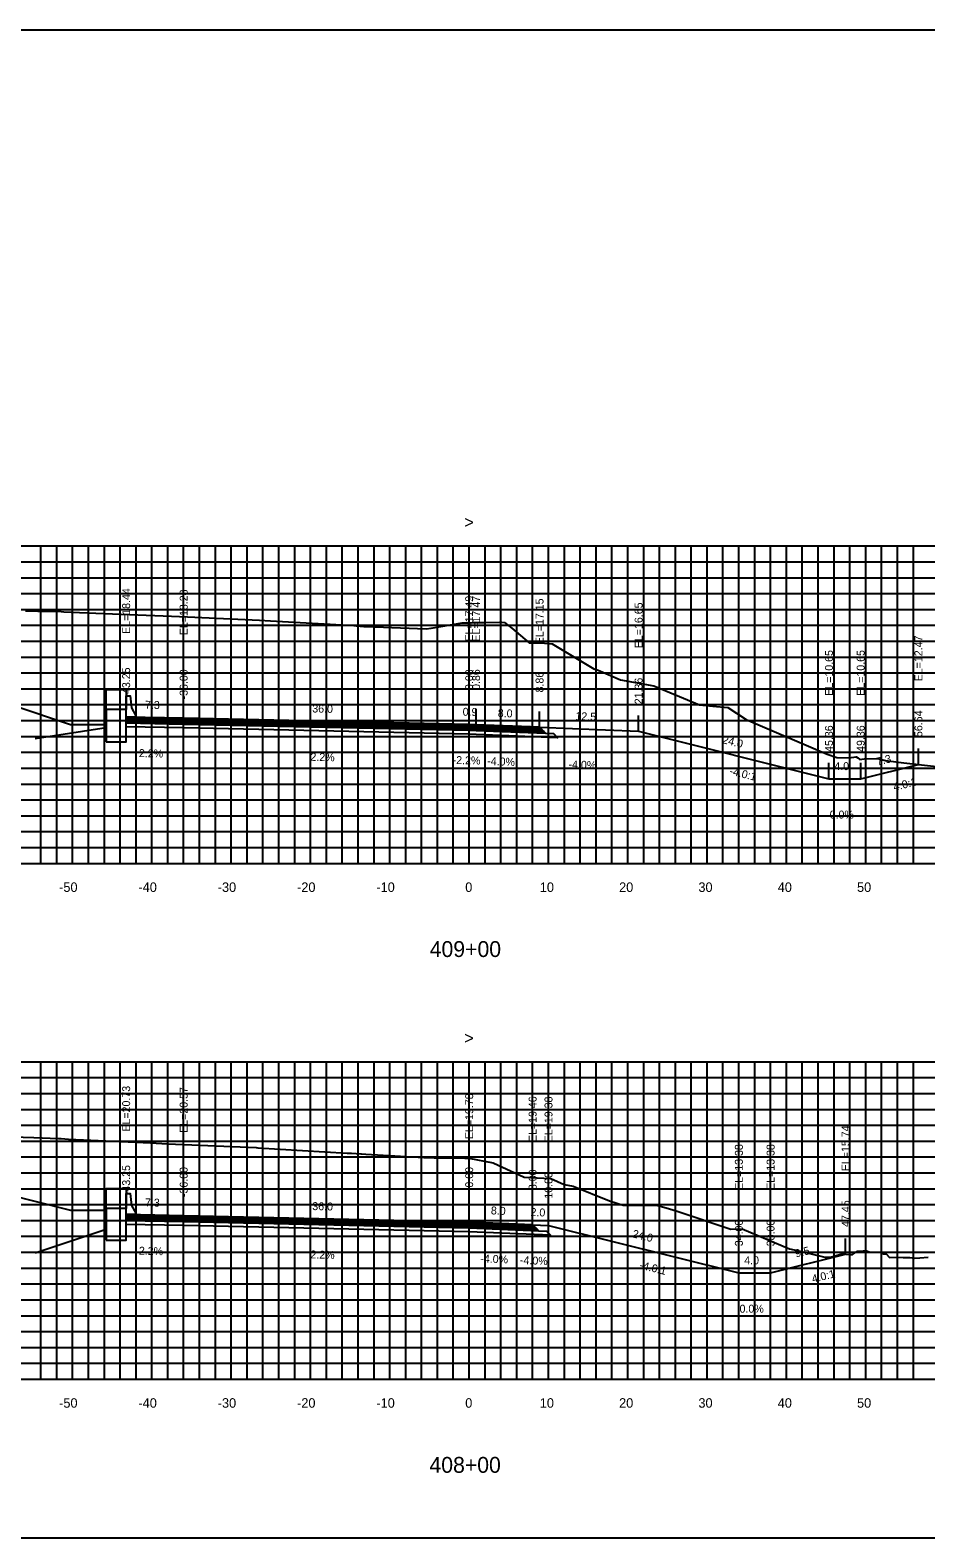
# Model space of a CAD drawing. Extents: x 1800976 to 1805104, y 250057 to 250580.
# Drawn here: x 1803595.6 to 1803708.6, y 250079.4 to 250269.4 of the extents above; entities that cross this region are included whole.
import ezdxf

# ---------------------------------------------------------------- set-up
doc = ezdxf.new("R2010")
doc.units = 0
for name, color, linetype in [('1', 7, 'Continuous'), ('10', 7, 'Continuous'), ('3', 7, 'Continuous'), ('4', 7, 'Continuous'), ('60', 7, 'Continuous'), ('BASE', 7, 'Continuous'), ('CL-CNST', 7, 'Continuous'), ('Default', 7, 'Continuous'), ('Level 62', 7, 'Continuous'), ('LOWER BINDER', 7, 'Continuous'), ('M-ROADS', 7, 'Continuous'), ('UPPER BINDER', 7, 'Continuous'), ('WEARING', 7, 'Continuous')]:
    doc.layers.add(name, color=color, linetype=linetype)

msp = doc.modelspace()

# ---------------------------------------------------------------- linework, layer by layer
for p, q in [((1803607.75, 250182.87), (1803607.75, 250184.87)), ((1803615, 250182.71), (1803615, 250184.71)), ((1803651, 250181.92), (1803651, 250183.92)), ((1803651.87, 250181.9), (1803651.87, 250183.9)), ((1803659.87, 250181.58), (1803659.87, 250183.58)), ((1803672.36, 250181.08), (1803672.36, 250183.08)), ((1803707.64, 250176.9), (1803707.64, 250178.9)), ((1803696.36, 250175.08), (1803696.36, 250177.08)), ((1803700.36, 250175.08), (1803700.36, 250177.08)), ((1803607.75, 250120.16), (1803607.75, 250122.16)), ((1803615, 250120), (1803615, 250122)), ((1803651, 250119.21), (1803651, 250121.21)), ((1803659, 250118.89), (1803659, 250120.89)), ((1803661, 250118.81), (1803661, 250120.81)), ((1803698.45, 250115.17), (1803698.45, 250117.17)), ((1803685, 250112.81), (1803685, 250114.81)), ((1803689, 250112.81), (1803689, 250114.81))]:
    msp.add_line(p, q)
msp.add_lwpolyline([(1803501, 250079.43), (1803801, 250079.43), (1803801, 250269.43), (1803501, 250269.43)], close=True)
at = {"layer": '3'}
for p, q in [((1803596.29, 250180.16), (1803605.25, 250181.54)), ((1803596.29, 250115.36), (1803605.25, 250118.35))]:
    msp.add_line(p, q, dxfattribs=at)
at = {"layer": '60'}
for p, q in [((1803501, 250164.43), (1803801, 250164.43)), ((1803601, 250164.37), (1803601, 250164.43)), ((1803611, 250164.37), (1803611, 250164.43)), ((1803621, 250164.37), (1803621, 250164.43)), ((1803631, 250164.37), (1803631, 250164.43)), ((1803641, 250164.37), (1803641, 250164.43)), ((1803651, 250164.37), (1803651, 250164.43)), ((1803661, 250164.37), (1803661, 250164.43)), ((1803671, 250164.37), (1803671, 250164.43)), ((1803681, 250164.37), (1803681, 250164.43)), ((1803691, 250164.37), (1803691, 250164.43)), ((1803701, 250164.37), (1803701, 250164.43)), ((1803501, 250099.43), (1803801, 250099.43)), ((1803601, 250099.37), (1803601, 250099.43)), ((1803611, 250099.37), (1803611, 250099.43)), ((1803621, 250099.37), (1803621, 250099.43)), ((1803631, 250099.37), (1803631, 250099.43)), ((1803641, 250099.37), (1803641, 250099.43)), ((1803651, 250099.37), (1803651, 250099.43)), ((1803661, 250099.37), (1803661, 250099.43)), ((1803671, 250099.37), (1803671, 250099.43)), ((1803681, 250099.37), (1803681, 250099.43)), ((1803691, 250099.37), (1803691, 250099.43)), ((1803701, 250099.37), (1803701, 250099.43))]:
    msp.add_line(p, q, dxfattribs=at)
at = {"layer": 'BASE'}
for points in [[(1803607.75, 250182.15), (1803615, 250181.99), (1803651, 250181.2), (1803651.87, 250181.18), (1803660.62, 250180.83), (1803661.62, 250180.79), (1803662.14, 250180.27), (1803651.87, 250180.68), (1803651, 250180.7), (1803615, 250181.49), (1803607.75, 250181.65)], [(1803607.75, 250119.44), (1803615, 250119.28), (1803651, 250118.49), (1803651, 250118.49), (1803659.75, 250118.14), (1803660.75, 250118.1), (1803661.27, 250117.58), (1803651, 250117.99), (1803651, 250117.99), (1803615, 250118.78), (1803607.75, 250118.94)]]:
    msp.add_lwpolyline(points, close=True, dxfattribs=at)
at = {"layer": 'CL-CNST'}
for p, q in [((1803600.75, 250181.95), (1803605.25, 250181.95)), ((1803600.75, 250120.73), (1803605.25, 250120.73))]:
    msp.add_line(p, q, dxfattribs=at)
for points in [[(1803501, 250197.17), (1803502.73, 250197.24), (1803511.65, 250197.57), (1803516.1, 250197.58), (1803523.71, 250197.56), (1803525.55, 250197.52), (1803529.73, 250197.42), (1803532.99, 250197.34), (1803541.8, 250197.13), (1803542.02, 250197.12), (1803542.8, 250197.09), (1803542.82, 250197.07), (1803542.88, 250197.02), (1803544.69, 250196.94), (1803551.86, 250196.64), (1803552.18, 250196.63), (1803553.87, 250196.56), (1803554.38, 250196.53), (1803557.4, 250196.41), (1803579.4, 250189.07), (1803600.75, 250181.95), (1803601.46, 250181.95), (1803605.24, 250181.95)], [(1803607.75, 250182.87), (1803615, 250182.71), (1803651, 250181.92), (1803651.87, 250181.9), (1803659.87, 250181.58), (1803672.36, 250181.08), (1803696.36, 250175.08), (1803700.36, 250175.08), (1803707.64, 250176.9)], [(1803580.55, 250125.79), (1803600.75, 250120.73), (1803602.94, 250120.73), (1803605.24, 250120.74)], [(1803607.75, 250120.16), (1803615, 250120), (1803651, 250119.21), (1803659, 250118.89), (1803661, 250118.81), (1803685, 250112.81), (1803689, 250112.81), (1803698.45, 250115.17)]]:
    msp.add_lwpolyline(points, dxfattribs=at)
for points in [[(1803607.75, 250183.83), (1803605.25, 250183.83), (1803605.25, 250186.33), (1803607.75, 250186.33)], [(1803605.25, 250179.73), (1803607.75, 250179.73), (1803607.75, 250183.83), (1803605.25, 250183.83)], [(1803607.75, 250120.94), (1803605.25, 250120.94), (1803605.25, 250123.44), (1803607.75, 250123.44)], [(1803605.25, 250116.93), (1803607.75, 250116.93), (1803607.75, 250120.94), (1803605.25, 250120.94)]]:
    msp.add_lwpolyline(points, close=True, dxfattribs=at)
at = {"layer": 'Default'}
for p, q in [((1803607.75, 250182.87), (1803607.75, 250185.54)), ((1803607.75, 250120.16), (1803607.75, 250122.83))]:
    msp.add_line(p, q, dxfattribs=at)
for points in [[(1803607.75, 250185.54), (1803608.25, 250185.54), (1803608.43, 250184.04), (1803608.98, 250183.04), (1803609, 250182.87), (1803607.75, 250182.87)], [(1803607.75, 250122.83), (1803608.25, 250122.83), (1803608.43, 250121.33), (1803608.98, 250120.33), (1803609, 250120.16), (1803607.75, 250120.16)]]:
    msp.add_lwpolyline(points, dxfattribs=at)
at = {"layer": 'Level 62'}
for p, q in [((1803501, 250204.43), (1803801, 250204.43)), ((1803597, 250164.43), (1803597, 250204.43)), ((1803599, 250164.43), (1803599, 250204.43)), ((1803601, 250164.43), (1803601, 250204.43)), ((1803603, 250164.43), (1803603, 250204.43)), ((1803605, 250164.43), (1803605, 250204.43)), ((1803607, 250164.43), (1803607, 250204.43)), ((1803609, 250164.43), (1803609, 250204.43)), ((1803611, 250164.43), (1803611, 250204.43)), ((1803613, 250164.43), (1803613, 250204.43)), ((1803615, 250164.43), (1803615, 250204.43)), ((1803617, 250164.43), (1803617, 250204.43)), ((1803619, 250164.43), (1803619, 250204.43)), ((1803621, 250164.43), (1803621, 250204.43)), ((1803623, 250164.43), (1803623, 250204.43)), ((1803625, 250164.43), (1803625, 250204.43)), ((1803627, 250164.43), (1803627, 250204.43)), ((1803629, 250164.43), (1803629, 250204.43)), ((1803631, 250164.43), (1803631, 250204.43)), ((1803633, 250164.43), (1803633, 250204.43)), ((1803635, 250164.43), (1803635, 250204.43)), ((1803637, 250164.43), (1803637, 250204.43)), ((1803639, 250164.43), (1803639, 250204.43)), ((1803641, 250164.43), (1803641, 250204.43)), ((1803643, 250164.43), (1803643, 250204.43)), ((1803645, 250164.43), (1803645, 250204.43)), ((1803647, 250164.43), (1803647, 250204.43)), ((1803649, 250164.43), (1803649, 250204.43)), ((1803651, 250164.43), (1803651, 250204.43)), ((1803653, 250164.43), (1803653, 250204.43)), ((1803655, 250164.43), (1803655, 250204.43)), ((1803657, 250164.43), (1803657, 250204.43)), ((1803659, 250164.43), (1803659, 250204.43)), ((1803661, 250164.43), (1803661, 250204.43)), ((1803663, 250164.43), (1803663, 250204.43)), ((1803665, 250164.43), (1803665, 250204.43)), ((1803667, 250164.43), (1803667, 250204.43)), ((1803669, 250164.43), (1803669, 250204.43)), ((1803671, 250164.43), (1803671, 250204.43)), ((1803673, 250164.43), (1803673, 250204.43)), ((1803675, 250164.43), (1803675, 250204.43)), ((1803677, 250164.43), (1803677, 250204.43)), ((1803679, 250164.43), (1803679, 250204.43)), ((1803681, 250164.43), (1803681, 250204.43)), ((1803683, 250164.43), (1803683, 250204.43)), ((1803685, 250164.43), (1803685, 250204.43)), ((1803687, 250164.43), (1803687, 250204.43)), ((1803689, 250164.43), (1803689, 250204.43)), ((1803691, 250164.43), (1803691, 250204.43)), ((1803693, 250164.43), (1803693, 250204.43)), ((1803695, 250164.43), (1803695, 250204.43)), ((1803697, 250164.43), (1803697, 250204.43)), ((1803699, 250164.43), (1803699, 250204.43)), ((1803701, 250164.43), (1803701, 250204.43)), ((1803703, 250164.43), (1803703, 250204.43)), ((1803705, 250164.43), (1803705, 250204.43)), ((1803707, 250164.43), (1803707, 250204.43)), ((1803501, 250202.43), (1803801, 250202.43)), ((1803501, 250200.43), (1803801, 250200.43)), ((1803501, 250198.43), (1803801, 250198.43)), ((1803501, 250196.43), (1803801, 250196.43)), ((1803501, 250194.43), (1803801, 250194.43)), ((1803501, 250192.43), (1803801, 250192.43)), ((1803501, 250190.43), (1803801, 250190.43)), ((1803501, 250188.43), (1803801, 250188.43)), ((1803501, 250186.43), (1803801, 250186.43)), ((1803501, 250184.43), (1803801, 250184.43)), ((1803501, 250182.43), (1803801, 250182.43)), ((1803501, 250180.43), (1803801, 250180.43)), ((1803501, 250178.43), (1803801, 250178.43)), ((1803501, 250176.43), (1803801, 250176.43)), ((1803501, 250174.43), (1803801, 250174.43)), ((1803501, 250172.43), (1803801, 250172.43)), ((1803501, 250170.43), (1803801, 250170.43)), ((1803501, 250168.43), (1803801, 250168.43)), ((1803501, 250166.43), (1803801, 250166.43)), ((1803501, 250164.43), (1803801, 250164.43)), ((1803501, 250139.43), (1803801, 250139.43)), ((1803597, 250099.43), (1803597, 250139.43)), ((1803599, 250099.43), (1803599, 250139.43)), ((1803601, 250099.43), (1803601, 250139.43)), ((1803603, 250099.43), (1803603, 250139.43)), ((1803605, 250099.43), (1803605, 250139.43)), ((1803607, 250099.43), (1803607, 250139.43)), ((1803609, 250099.43), (1803609, 250139.43)), ((1803611, 250099.43), (1803611, 250139.43)), ((1803613, 250099.43), (1803613, 250139.43)), ((1803615, 250099.43), (1803615, 250139.43)), ((1803617, 250099.43), (1803617, 250139.43)), ((1803619, 250099.43), (1803619, 250139.43)), ((1803621, 250099.43), (1803621, 250139.43)), ((1803623, 250099.43), (1803623, 250139.43)), ((1803625, 250099.43), (1803625, 250139.43)), ((1803627, 250099.43), (1803627, 250139.43)), ((1803629, 250099.43), (1803629, 250139.43)), ((1803631, 250099.43), (1803631, 250139.43)), ((1803633, 250099.43), (1803633, 250139.43)), ((1803635, 250099.43), (1803635, 250139.43)), ((1803637, 250099.43), (1803637, 250139.43)), ((1803639, 250099.43), (1803639, 250139.43)), ((1803641, 250099.43), (1803641, 250139.43)), ((1803643, 250099.43), (1803643, 250139.43)), ((1803645, 250099.43), (1803645, 250139.43)), ((1803647, 250099.43), (1803647, 250139.43)), ((1803649, 250099.43), (1803649, 250139.43)), ((1803651, 250099.43), (1803651, 250139.43)), ((1803653, 250099.43), (1803653, 250139.43)), ((1803655, 250099.43), (1803655, 250139.43)), ((1803657, 250099.43), (1803657, 250139.43)), ((1803659, 250099.43), (1803659, 250139.43)), ((1803661, 250099.43), (1803661, 250139.43)), ((1803663, 250099.43), (1803663, 250139.43)), ((1803665, 250099.43), (1803665, 250139.43)), ((1803667, 250099.43), (1803667, 250139.43)), ((1803669, 250099.43), (1803669, 250139.43)), ((1803671, 250099.43), (1803671, 250139.43)), ((1803673, 250099.43), (1803673, 250139.43)), ((1803675, 250099.43), (1803675, 250139.43)), ((1803677, 250099.43), (1803677, 250139.43)), ((1803679, 250099.43), (1803679, 250139.43)), ((1803681, 250099.43), (1803681, 250139.43)), ((1803683, 250099.43), (1803683, 250139.43)), ((1803685, 250099.43), (1803685, 250139.43)), ((1803687, 250099.43), (1803687, 250139.43)), ((1803689, 250099.43), (1803689, 250139.43)), ((1803691, 250099.43), (1803691, 250139.43)), ((1803693, 250099.43), (1803693, 250139.43)), ((1803695, 250099.43), (1803695, 250139.43)), ((1803697, 250099.43), (1803697, 250139.43)), ((1803699, 250099.43), (1803699, 250139.43)), ((1803701, 250099.43), (1803701, 250139.43)), ((1803703, 250099.43), (1803703, 250139.43)), ((1803705, 250099.43), (1803705, 250139.43)), ((1803707, 250099.43), (1803707, 250139.43)), ((1803501, 250137.43), (1803801, 250137.43)), ((1803501, 250135.43), (1803801, 250135.43)), ((1803501, 250133.43), (1803801, 250133.43)), ((1803501, 250131.43), (1803801, 250131.43)), ((1803501, 250129.43), (1803801, 250129.43)), ((1803501, 250127.43), (1803801, 250127.43)), ((1803501, 250125.43), (1803801, 250125.43)), ((1803501, 250123.43), (1803801, 250123.43)), ((1803501, 250121.43), (1803801, 250121.43)), ((1803501, 250119.43), (1803801, 250119.43)), ((1803501, 250117.43), (1803801, 250117.43)), ((1803501, 250115.43), (1803801, 250115.43)), ((1803501, 250113.43), (1803801, 250113.43)), ((1803501, 250111.43), (1803801, 250111.43)), ((1803501, 250109.43), (1803801, 250109.43)), ((1803501, 250107.43), (1803801, 250107.43)), ((1803501, 250105.43), (1803801, 250105.43)), ((1803501, 250103.43), (1803801, 250103.43)), ((1803501, 250101.43), (1803801, 250101.43)), ((1803501, 250099.43), (1803801, 250099.43))]:
    msp.add_line(p, q, dxfattribs=at)
at = {"layer": 'LOWER BINDER'}
for points in [[(1803615, 250182.37), (1803651, 250181.58), (1803651.87, 250181.56), (1803660.22, 250181.22), (1803660.42, 250181.03), (1803651.87, 250181.37), (1803651, 250181.39), (1803615, 250182.18), (1803607.75, 250182.34), (1803607.75, 250182.53)], [(1803615, 250182.18), (1803651, 250181.39), (1803651.87, 250181.37), (1803660.42, 250181.03), (1803660.62, 250180.83), (1803651.87, 250181.18), (1803651, 250181.2), (1803615, 250181.99), (1803607.75, 250182.15), (1803607.75, 250182.34)], [(1803615, 250119.66), (1803651, 250118.87), (1803651, 250118.87), (1803659.36, 250118.53), (1803659.55, 250118.34), (1803651, 250118.68), (1803651, 250118.68), (1803615, 250119.47), (1803607.75, 250119.63), (1803607.75, 250119.82)], [(1803615, 250119.47), (1803651, 250118.68), (1803651, 250118.68), (1803659.55, 250118.34), (1803659.75, 250118.14), (1803651, 250118.49), (1803651, 250118.49), (1803615, 250119.28), (1803607.75, 250119.44), (1803607.75, 250119.63)]]:
    msp.add_lwpolyline(points, close=True, dxfattribs=at)
at = {"layer": 'M-ROADS'}
for points in [[(1803595.07, 250196.24), (1803596.6, 250196.21), (1803599.57, 250196.15), (1803599.91, 250196.13), (1803600.82, 250196.09), (1803603.92, 250195.97), (1803613.45, 250195.58), (1803615.5, 250195.49), (1803624.58, 250195.08), (1803625.95, 250195), (1803636.47, 250194.4), (1803636.73, 250194.38), (1803637.72, 250194.3), (1803639.1, 250194.24), (1803645.57, 250193.97), (1803646.2, 250194.08), (1803650.11, 250194.76), (1803650.8, 250194.73), (1803651.36, 250194.78), (1803652.9, 250194.8), (1803654.81, 250194.82), (1803655.13, 250194.81), (1803655.47, 250194.8), (1803656.36, 250194.07), (1803658.58, 250192.23), (1803660.04, 250192.23), (1803661.47, 250192.08), (1803666.7, 250188.94), (1803667.27, 250188.79), (1803670.08, 250187.57), (1803674.3, 250186.8), (1803680.03, 250184.4), (1803681.72, 250184.24), (1803683.63, 250184.06), (1803685.93, 250182.58), (1803696.15, 250178.21), (1803697.37, 250177.76), (1803698.87, 250177.72), (1803699.78, 250177.86), (1803700, 250177.71), (1803700.26, 250177.53), (1803701.05, 250177.66), (1803702.71, 250177.61), (1803703.5, 250177.41), (1803705.82, 250177.11), (1803709.91, 250176.63)], [(1803589.37, 250130.1), (1803596.13, 250129.87), (1803599.22, 250129.76), (1803599.57, 250129.75), (1803600.48, 250129.69), (1803610.82, 250129.2), (1803612.96, 250129.09), (1803624.16, 250128.61), (1803624.34, 250128.6), (1803635.63, 250127.92), (1803636.17, 250127.89), (1803637.35, 250127.81), (1803637.43, 250127.81), (1803637.97, 250127.78), (1803645.29, 250127.35), (1803646.58, 250127.31), (1803650.45, 250127.29), (1803650.77, 250127.29), (1803650.97, 250127.29), (1803654.02, 250126.69), (1803657.94, 250124.88), (1803660.41, 250124.74), (1803661.3, 250124.7), (1803662.99, 250123.98), (1803664.11, 250123.75), (1803668.68, 250121.9), (1803669.62, 250121.6), (1803670.42, 250121.35), (1803672.09, 250121.35), (1803672.61, 250121.35), (1803674.6, 250121.35), (1803675.85, 250121), (1803677.11, 250120.64), (1803683.97, 250118.32), (1803685.42, 250118.38), (1803691.4, 250115.87), (1803692.75, 250115.55), (1803695.84, 250114.79), (1803696.09, 250114.82), (1803696.57, 250114.81), (1803698, 250115.21), (1803699.03, 250115.12), (1803699.31, 250115.16), (1803699.97, 250115.56), (1803700.69, 250115.59), (1803701.09, 250115.6), (1803701.57, 250115.45), (1803701.87, 250115.45), (1803702.93, 250115.4), (1803703.23, 250115.22), (1803703.58, 250115.21), (1803704.01, 250114.78), (1803704.86, 250114.81), (1803705.71, 250114.77), (1803706.35, 250114.77), (1803706.49, 250114.78), (1803706.54, 250114.77), (1803707.15, 250114.69), (1803707.8, 250114.73), (1803708.85, 250114.8)]]:
    msp.add_lwpolyline(points, dxfattribs=at)
at = {"layer": 'UPPER BINDER'}
for points in [[(1803651.87, 250181.56), (1803660.22, 250181.22), (1803660.02, 250181.42), (1803651.87, 250181.75), (1803651, 250181.77), (1803615, 250182.56), (1803607.75, 250182.72), (1803607.75, 250182.53), (1803615, 250182.37), (1803651, 250181.58)], [(1803651, 250118.87), (1803659.36, 250118.53), (1803659.16, 250118.73), (1803651, 250119.06), (1803651, 250119.06), (1803615, 250119.85), (1803607.75, 250120.01), (1803607.75, 250119.82), (1803615, 250119.66), (1803651, 250118.87)]]:
    msp.add_lwpolyline(points, close=True, dxfattribs=at)
at = {"layer": 'WEARING'}
for points in [[(1803651.87, 250181.75), (1803660.02, 250181.42), (1803659.87, 250181.58), (1803651.87, 250181.9), (1803651, 250181.92), (1803615, 250182.71), (1803607.75, 250182.87), (1803607.75, 250182.72), (1803615, 250182.56), (1803651, 250181.77)], [(1803651, 250119.06), (1803659.16, 250118.73), (1803659, 250118.89), (1803651, 250119.21), (1803651, 250119.21), (1803615, 250120), (1803607.75, 250120.16), (1803607.75, 250120.01), (1803615, 250119.85), (1803651, 250119.06)]]:
    msp.add_lwpolyline(points, close=True, dxfattribs=at)

# ---------------------------------------------------------------- texts
for s, rotation, p in [('-4.0:1', 345.9638, (1803683.75, 250175.65)), ('4.0:1', 14.0362, (1803704.61, 250173.56)), ('-4.0:1', 345.9638, (1803672.4, 250113.38)), ('4.0:1', 14.0362, (1803694.33, 250111.56))]:
    msp.add_text(s, height=1, rotation=rotation).set_placement(p)
at = {"layer": '1'}
for s, p in [('409+00', (1803646.02, 250152.63)), ('408+00', (1803645.99, 250087.63))]:
    msp.add_text(s, height=2, dxfattribs=at).set_placement(p)
at = {"layer": '10'}
for s, p in [('-50', (1803599.3, 250160.83)), ('-40', (1803609.3, 250160.83)), ('-30', (1803619.3, 250160.83)), ('-20', (1803629.3, 250160.83)), ('-10', (1803639.3, 250160.83)), ('0', (1803650.5, 250160.83)), ('10', (1803659.9, 250160.83)), ('20', (1803669.9, 250160.83)), ('30', (1803679.9, 250160.83)), ('40', (1803689.9, 250160.83)), ('50', (1803699.9, 250160.83)), ('-50', (1803599.3, 250095.83)), ('-40', (1803609.3, 250095.83)), ('-30', (1803619.3, 250095.83)), ('-20', (1803629.3, 250095.83)), ('-10', (1803639.3, 250095.83)), ('0', (1803650.5, 250095.83)), ('10', (1803659.9, 250095.83)), ('20', (1803669.9, 250095.83)), ('30', (1803679.9, 250095.83)), ('40', (1803689.9, 250095.83)), ('50', (1803699.9, 250095.83))]:
    msp.add_text(s, height=1.2, dxfattribs=at).set_placement(p)
at = {"layer": '3'}
for s, p in [('EL=18.44', (1803608.25, 250193.34)), ('EL=18.28', (1803615.5, 250193.18)), ('EL=17.49', (1803651.5, 250192.39)), ('EL=17.47', (1803652.37, 250192.37)), ('EL=17.15', (1803660.37, 250192.05)), ('EL=16.65', (1803672.86, 250191.55)), ('EL=12.47', (1803708.14, 250187.37)), ('EL=10.65', (1803696.86, 250185.55)), ('EL=10.65', (1803700.86, 250185.55)), ('-43.25', (1803608.25, 250185.33)), ('-36.00', (1803615.5, 250185.09)), ('0.00', (1803651.5, 250186.28)), ('0.86', (1803652.37, 250186.29)), ('8.86', (1803660.37, 250185.97)), ('21.36', (1803672.86, 250184.48)), ('56.64', (1803708.14, 250180.35)), ('45.36', (1803696.86, 250178.48)), ('49.36', (1803700.86, 250178.48)), ('EL=20.73', (1803608.25, 250130.63)), ('EL=20.57', (1803615.5, 250130.47)), ('EL=19.78', (1803651.5, 250129.68)), ('EL=19.46', (1803659.5, 250129.31)), ('EL=19.38', (1803661.5, 250129.28)), ('EL=15.74', (1803698.95, 250125.64)), ('EL=13.38', (1803685.5, 250123.28)), ('EL=13.38', (1803689.5, 250123.28)), ('-43.25', (1803608.25, 250122.62)), ('-36.00', (1803615.5, 250122.38)), ('0.00', (1803651.5, 250123.57)), ('8.00', (1803659.5, 250123.25)), ('10.00', (1803661.5, 250122.18)), ('47.45', (1803698.95, 250118.62)), ('34.00', (1803685.5, 250116.18)), ('38.00', (1803689.5, 250116.18))]:
    msp.add_text(s, height=1, rotation=90, dxfattribs=at).set_placement(p)
at = {"layer": '4'}
for s, rotation, p in [('7.3', 358.7397, (1803610.12, 250183.92)), ('36.0', 358.7397, (1803631.21, 250183.45)), ('0.9', 358.7397, (1803650.17, 250183.04)), ('8.0', 357.7094, (1803654.59, 250182.89)), ('12.5', 357.7094, (1803664.38, 250182.5)), ('2.2%', 358.7397, (1803609.35, 250177.83)), ('24.0', 345.9638, (1803682.86, 250179.59)), ('2.2%', 358.7397, (1803630.98, 250177.36)), ('-2.2%', 358.7397, (1803648.91, 250176.96)), ('-4.0%', 357.7094, (1803653.26, 250176.84)), ('-4.0%', 357.7094, (1803663.51, 250176.43)), ('7.3', 14.0362, (1803702.49, 250176.74)), ('7.3', 358.7397, (1803610.12, 250121.21)), ('36.0', 358.7397, (1803631.21, 250120.74)), ('8.0', 357.7094, (1803653.72, 250120.2)), ('2.0', 357.7094, (1803658.72, 250120)), ('24.0', 345.9638, (1803671.5, 250117.32)), ('2.2%', 358.7397, (1803609.35, 250115.12)), ('9.5', 14.0362, (1803692.21, 250114.75)), ('2.2%', 358.7397, (1803630.98, 250114.65)), ('-4.0%', 357.7094, (1803652.39, 250114.15)), ('-4.0%', 357.7094, (1803657.39, 250113.95))]:
    msp.add_text(s, height=1, rotation=rotation, dxfattribs=at).set_placement(p)
for s, p in [('4.0', (1803697.04, 250176.18)), ('0.0%', (1803696.45, 250170.08)), ('4.0', (1803685.68, 250113.91)), ('0.0%', (1803685.09, 250107.81))]:
    msp.add_text(s, height=1, dxfattribs=at).set_placement(p)
at = {"layer": '60'}
for p in [(1803650.39, 250206.68), (1803650.39, 250141.68)]:
    msp.add_text('>', height=1.5, dxfattribs=at).set_placement(p)

doc.saveas('drawing.dxf')
